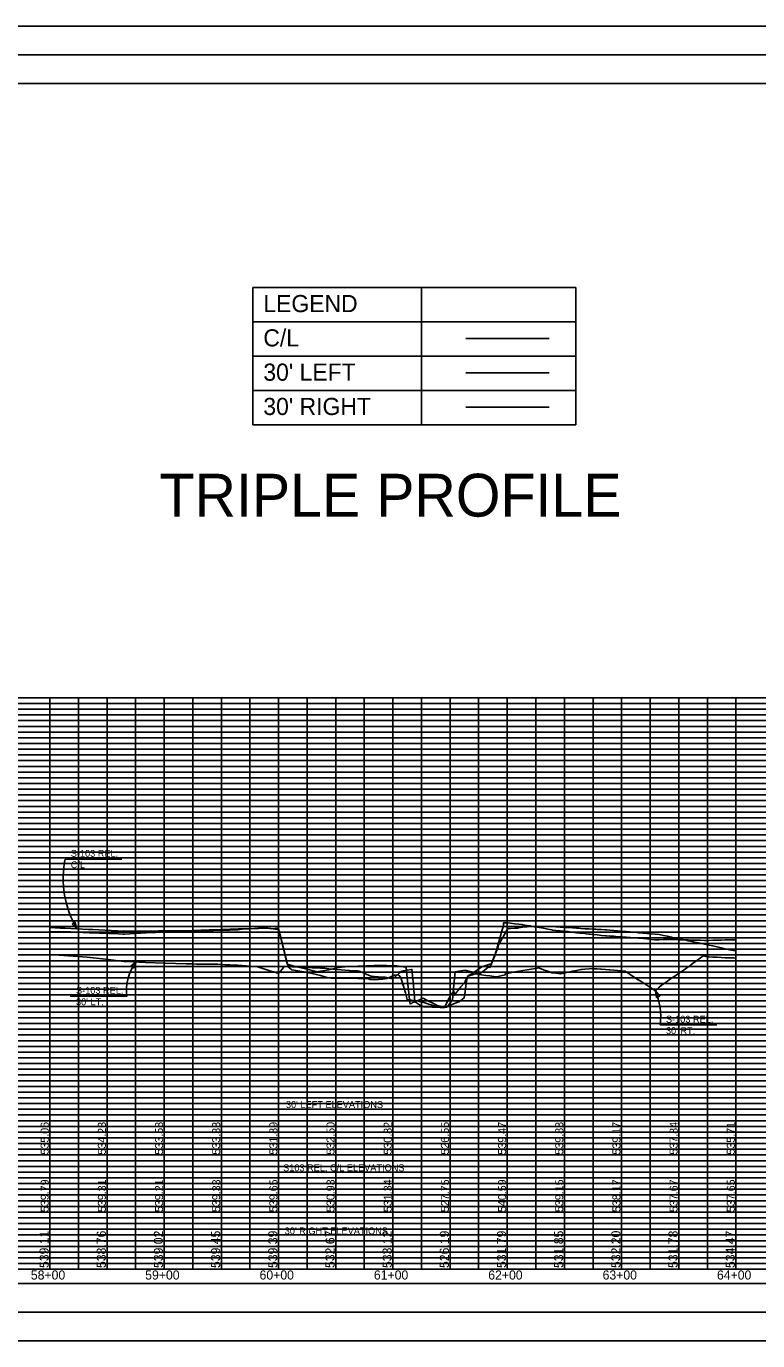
# Model space of a CAD drawing. Extents: x 49817 to 52197, y 49938 to 51088.
# Drawn here: x 50379 to 51019, y 49938 to 51088 of the extents above; entities that cross this region are included whole.
import ezdxf

# ---------------------------------------------------------------- set-up
doc = ezdxf.new("R2010")
doc.units = 0
for name, color, linetype in [('RD_DDB_Profile_EX', 7, 'Continuous'), ('RD_DDB_StaTX', 7, 'Continuous'), ('RD_DDB_StripGrade', 7, 'Continuous'), ('RD_GPK_Profile_Cell', 7, 'Continuous'), ('RD_SHT_Bndy', 7, 'Continuous'), ('RD_SHT_Iplotshp', 7, 'Continuous'), ('RD_SHT_MjGrid', 7, 'Continuous'), ('RD_SHT_MnGrid', 7, 'Continuous'), ('RD_SHT_SubGrid', 7, 'Continuous'), ('RD_TX_Misc2', 7, 'Continuous'), ('RD_TX_Profile', 7, 'Continuous')]:
    doc.layers.add(name, color=color, linetype=linetype)

msp = doc.modelspace()

# ---------------------------------------------------------------- linework, layer by layer
at = {"layer": 'RD_DDB_Profile_EX'}
for points in [[(50750.5, 50239.7), (50752.3, 50242.2), (50753.4, 50243.6), (50753.9, 50239.7), (50755.9, 50242.6), (50756.7, 50243.6), (50759.5, 50247), (50762.5, 50250.5), (50763.2, 50251.9), (50764.2, 50253.9), (50765.6, 50256.1), (50766.2, 50256.9), (50766.8, 50257.3), (50770.4, 50259.7), (50774, 50262.1), (50777.7, 50264.5), (50781.2, 50265.7), (50784.8, 50266.8), (50785.9, 50267.1), (50786.3, 50267.2), (50788.4, 50272.3), (50788.9, 50273.5), (50792, 50284.4), (50795.7, 50297.1), (50796.6, 50300.5), (50796.8, 50303.2), (50799.3, 50303), (50800.3, 50303), (50802.9, 50302.7), (50806.5, 50302.3), (50810.1, 50301.9), (50813.1, 50301.6), (50813.7, 50301.5), (50817.3, 50300.9), (50820.1, 50300.4), (50821, 50300.2), (50823.6, 50299.7), (50824.6, 50299.6), (50828.2, 50298.9), (50831.8, 50298.3), (50835.4, 50297.6), (50839, 50296.9), (50839.4, 50296.8), (50840, 50296.7), (50842.6, 50296.5), (50846.2, 50296.1), (50849.8, 50295.8), (50853, 50295.5), (50853.4, 50295.4), (50857.1, 50294.9), (50860.7, 50294.5), (50863.6, 50294.1), (50864.3, 50294), (50867.9, 50293.7), (50869.1, 50293.6), (50871.5, 50293.3), (50872.4, 50293.2), (50875.1, 50292.9), (50878.7, 50292.5), (50882.3, 50292.1), (50885.9, 50291.7), (50886.7, 50291.7), (50889.6, 50291.5), (50893.2, 50291.3), (50896.8, 50291), (50900.4, 50290.8), (50904, 50290.6), (50907.6, 50290.3), (50910.6, 50290.1), (50911.2, 50290.1), (50911.6, 50290.1), (50914.8, 50289.8), (50918.5, 50289.6), (50919.4, 50289.5), (50922.1, 50289.2), (50925.7, 50288.6), (50928.8, 50288.1), (50929.4, 50288.1), (50932.9, 50288.3), (50936.5, 50288.5), (50939.7, 50288.6), (50940.1, 50288.6), (50943.7, 50288.5), (50947.3, 50288.4), (50951, 50288.3), (50952.6, 50288.3), (50954.6, 50288.2), (50958.2, 50288.1), (50961.8, 50288), (50965.4, 50287.9), (50969, 50287.8), (50972.6, 50287.7), (50976.3, 50287.6), (50979.8, 50287.8), (50983.5, 50287.9), (50986.7, 50288), (50987.1, 50288), (50990.7, 50288.1), (50994.3, 50288.1), (50997.9, 50288.2), (51000, 50288.2)], [(50400, 50299), (50408.9, 50298.5), (50413.5, 50298.3), (50433.9, 50297.3), (50437.5, 50297.2), (50459, 50296.1), (50459.3, 50296.1), (50462.3, 50295.9), (50464.8, 50296), (50487.2, 50295.9), (50495, 50296), (50512.2, 50296), (50521.2, 50296.2), (50523.2, 50296.2), (50524.8, 50296.2), (50528.4, 50296.2), (50532, 50296.3), (50535.6, 50296.3), (50537.2, 50296.3), (50539.2, 50296.4), (50542.9, 50296.5), (50546.5, 50296.6), (50550.1, 50296.7), (50551, 50296.7), (50553.7, 50296.8), (50557.3, 50296.8), (50560.9, 50296.9), (50562.2, 50297), (50563.5, 50297), (50564.5, 50297.1), (50568.1, 50297.5), (50570.8, 50297.8), (50571.7, 50297.8), (50575.4, 50298), (50579, 50298.2), (50582.6, 50298.4), (50586.2, 50298.5), (50588.7, 50298.7), (50589.8, 50298.7), (50593.6, 50298), (50597, 50298.1), (50598.7, 50298.1), (50600, 50298.2), (50600.6, 50295.5), (50601.3, 50292.5), (50604.3, 50281.1), (50607.9, 50267.1), (50608.6, 50264.3), (50611.6, 50262.1), (50615.1, 50261.4), (50618.7, 50260.8), (50622.3, 50260.1), (50625.9, 50259.4), (50628.3, 50259), (50629.5, 50258.7), (50633.1, 50257.8), (50636.8, 50256.9), (50640.4, 50256), (50644, 50255.1), (50645.9, 50254.6), (50647.6, 50254.7), (50651.2, 50254.7), (50654.8, 50254.7), (50655.6, 50254.7), (50658.4, 50254.6), (50662, 50254.6), (50665.6, 50254.6), (50669.3, 50254.5), (50672.9, 50254.5), (50676.5, 50254.4), (50677.9, 50254.4), (50680.1, 50253.4), (50683.8, 50253.2), (50687.3, 50253.5), (50691.1, 50253.9), (50694.7, 50254.3), (50698.2, 50255.9), (50701.3, 50257.3), (50701.8, 50257.3), (50704.8, 50257.5), (50705.4, 50256.9), (50707, 50254.9), (50709, 50248.6), (50711.1, 50241.8), (50712.4, 50236), (50716.2, 50235.5), (50719.8, 50235), (50720.7, 50234.9), (50722.4, 50234.7), (50723.4, 50234.4), (50725.3, 50233.8), (50727, 50233.3), (50730.7, 50232.2), (50734.3, 50231.2), (50737.9, 50230.1), (50741.7, 50228.9), (50744.6, 50228.7), (50745.1, 50229.4), (50745.7, 50230.3), (50748.7, 50236.2), (50750.5, 50239.7)], [(50400, 50295.6), (50409.8, 50295.3), (50418, 50295.1), (50434.7, 50294.4), (50435.2, 50294.4), (50459.9, 50293.4), (50463.9, 50293.2), (50465.3, 50293.3), (50488.8, 50294.6), (50492.5, 50294.7), (50513.8, 50295.8), (50519.4, 50296), (50521.2, 50296.1), (50524.8, 50296.3), (50528.4, 50296.4), (50532, 50296.6), (50535.6, 50296.8), (50539.2, 50296.9), (50542.9, 50297), (50546, 50297.1), (50546.5, 50297.1), (50550.1, 50297.2), (50553.7, 50297.4), (50557.3, 50297.5), (50560.9, 50297.7), (50564.7, 50297.8), (50568.1, 50297.8), (50572, 50297.9), (50575.4, 50298), (50579, 50298.1), (50582.6, 50298.2), (50586.2, 50298.3), (50589.8, 50298.5), (50590.2, 50298.5), (50593.4, 50298.1), (50597, 50297.7), (50599.5, 50297.4), (50600.3, 50296.7), (50600.6, 50295.3), (50604.3, 50280.5), (50607.6, 50266.8), (50611.5, 50265.9), (50615.1, 50265), (50618.7, 50264.1), (50622.3, 50263.2), (50625.9, 50262.3), (50629.5, 50261.4), (50631.8, 50260.8), (50633.1, 50260.4), (50634.5, 50260.1), (50635.3, 50260.4), (50636.8, 50260.7), (50640.4, 50261.4), (50644, 50262.1), (50647.6, 50262.9), (50651.2, 50263.6), (50655, 50264.4), (50658.4, 50264.6), (50662, 50264.8), (50665.6, 50264.9), (50669.3, 50265.1), (50672.9, 50265.3), (50676.5, 50265.5), (50678.2, 50265.6), (50680.1, 50265.6), (50683.7, 50265.7), (50685.7, 50265.7), (50687.3, 50265.7), (50690.9, 50265.7), (50694.5, 50265.7), (50698.2, 50265.6), (50701.8, 50265.6), (50703.3, 50265.6), (50705.4, 50265.2), (50709, 50264.6), (50711.7, 50264.2), (50712.6, 50255), (50714.7, 50233.5), (50715, 50232.2), (50716.2, 50232.6), (50717, 50233), (50719.8, 50234.2), (50723.4, 50235.7), (50726.6, 50237.1), (50727, 50236.9), (50730.7, 50235), (50734.3, 50233.2), (50737.9, 50231.4), (50738.8, 50230.9), (50741.5, 50230.2), (50745.1, 50229.3), (50745.5, 50229.2), (50748.7, 50230.4), (50752.3, 50231.9), (50755.9, 50233.3), (50758.2, 50234.1), (50759.5, 50235.2), (50762.3, 50237.4), (50763.2, 50243.1), (50764.2, 50250.2), (50765.1, 50256.2)], [(50775.9, 50258.9), (50776.3, 50258.8), (50777.6, 50259.6), (50781.2, 50262.6), (50783.4, 50264.3), (50784.8, 50263.9), (50788.4, 50272.7), (50791.3, 50279.8), (50792, 50282.4), (50792.5, 50284), (50795.7, 50289.5), (50797.6, 50292.9), (50799.3, 50296), (50800.4, 50298.1), (50802.9, 50298.2), (50806.5, 50298.3), (50809.1, 50298.4), (50810.1, 50298.6), (50813.2, 50299.3), (50813.7, 50299.3), (50817.3, 50299.6), (50820.9, 50299.8), (50824.6, 50300), (50825.3, 50300.1), (50828.2, 50300), (50831.8, 50299.9), (50835.4, 50299.8), (50836.2, 50299.8), (50837.9, 50299.9), (50839, 50299.8), (50842.6, 50299.6), (50846.2, 50299.4), (50849.8, 50299.1), (50850.5, 50299.1), (50853.4, 50298.9), (50857.1, 50298.7), (50860.7, 50298.5), (50862.2, 50298.4), (50864.3, 50298.2), (50867.9, 50298), (50871.5, 50297.8), (50875.1, 50297.6), (50877.4, 50297.5), (50878.7, 50297.4), (50882.3, 50297.2), (50885.6, 50297), (50885.9, 50297), (50887, 50296.9), (50889.6, 50296.7), (50893.2, 50296.4), (50896.5, 50296.2), (50896.8, 50296.2), (50900.4, 50295.8), (50904, 50295.5), (50907.6, 50295.1), (50911.2, 50294.8), (50911.6, 50294.8), (50914.8, 50294.5), (50916.3, 50294.4), (50918.5, 50294.2), (50922.1, 50293.9), (50925.7, 50293.5), (50929.3, 50293.2), (50932.9, 50292.8), (50934.2, 50292.7), (50936.5, 50292.1), (50940.1, 50291.3), (50943.7, 50290.6), (50947.3, 50289.8), (50951, 50289), (50954.6, 50288.2), (50957.4, 50287.7), (50958.2, 50287.5), (50961.8, 50286.7), (50963.5, 50286.3), (50965.4, 50285.9), (50969, 50285.2), (50972.6, 50284.4), (50976.2, 50283.7), (50979.4, 50283.1), (50979.8, 50283), (50983.5, 50282.1), (50987.1, 50281.3), (50990.7, 50280.4), (50994.3, 50279.6), (50996.2, 50279.1), (50997.9, 50278.9), (51000, 50278.5)], [(50400, 50275.3), (50432.7, 50273.2), (50448.7, 50271.3), (50464.8, 50269.4), (50467.2, 50269.2), (50483.6, 50268.5), (50501, 50267.9), (50519.3, 50267.2), (50521.2, 50267.1), (50524.8, 50267.1), (50528.4, 50267), (50532, 50267), (50535.6, 50266.9), (50539.2, 50266.9), (50542.9, 50266.8), (50546.5, 50266.8), (50550.1, 50266.6), (50553.7, 50266.5), (50557.3, 50266.4), (50560.9, 50266.2), (50562.9, 50266.1), (50564.5, 50266), (50568.1, 50265.7), (50571.7, 50265.5), (50575.4, 50265.2), (50579, 50264.9), (50581.3, 50264.8), (50582.6, 50264.3), (50586.2, 50263.2), (50589.8, 50262.1), (50593.4, 50260.9), (50597, 50259.8), (50598.2, 50259.4), (50600.6, 50259.5), (50604.3, 50263.9), (50605.1, 50264.9), (50607.9, 50264.8), (50611.5, 50264.6), (50615.1, 50264.5), (50618.7, 50264.3), (50622.3, 50264.1), (50625.9, 50263.9), (50629.5, 50263.8), (50633.1, 50263.6), (50636.8, 50263.4), (50639.8, 50263.3), (50640.4, 50263.3), (50644, 50263), (50647.6, 50262.7), (50651.2, 50262.4), (50654.8, 50262.1), (50658.4, 50261.8), (50662, 50261.5), (50665.6, 50261.2), (50669.3, 50261), (50670.6, 50260.9), (50672.9, 50259.8), (50676.5, 50258.2), (50680.1, 50256.6), (50680.9, 50256.3), (50683.7, 50256.1), (50687.3, 50255.9), (50690.9, 50255.7), (50693.3, 50255.5), (50694.5, 50255.3), (50698.2, 50254.5), (50700.1, 50254.1), (50701.8, 50255.7), (50705.4, 50259.2), (50706.8, 50260.6), (50709, 50261), (50712.6, 50261.7), (50716.2, 50262.4), (50716.7, 50262.5), (50717.8, 50251.4), (50719.2, 50234.2), (50719.8, 50233.8), (50723.4, 50231.5), (50724.4, 50230.9), (50727.1, 50229.6), (50730.7, 50229.5), (50734.3, 50229.4), (50737.9, 50229.3), (50741.5, 50229.2), (50743.3, 50229.2), (50745.1, 50229.2), (50747.2, 50229.3), (50748.3, 50230.5), (50748.7, 50231.1), (50752.2, 50235.6), (50753.4, 50248.9), (50754.5, 50260.2), (50755.9, 50260.5), (50759.5, 50261.1), (50763.2, 50261.6), (50766.8, 50260.8), (50770.4, 50260), (50774, 50259.2), (50774.6, 50259.1), (50775.4, 50259.2), (50775.9, 50258.9)], [(50765.1, 50256.2), (50766.8, 50256.8), (50770.4, 50258), (50771.7, 50258.4), (50774, 50258.1), (50777.6, 50257.6), (50781.2, 50257.1), (50784.8, 50256.6), (50788.4, 50256.1), (50790.7, 50255.8), (50792, 50256.1), (50795.7, 50256.9), (50797.5, 50257.3), (50798.8, 50258.9), (50799.3, 50258.9), (50800, 50258.9), (50802.9, 50259.5), (50806.5, 50260.1), (50810.1, 50260.7), (50813.7, 50261.3), (50817.3, 50261.9), (50820.9, 50262.5), (50824.6, 50263.1), (50827.8, 50263.6), (50828.2, 50263.5), (50831.8, 50262.1), (50835.4, 50260.8), (50837, 50260.1), (50839.1, 50259.4), (50842.6, 50259), (50846.2, 50258.6), (50846.7, 50258.5), (50849.8, 50259.2), (50853.4, 50260), (50856.2, 50260.5), (50857.1, 50260.7), (50860.7, 50261.4), (50864.3, 50262.2), (50865.6, 50262.4), (50867.9, 50262.7), (50871.5, 50263), (50873, 50263.2), (50875.1, 50263), (50878.7, 50262.8), (50881.5, 50262.6), (50882.3, 50262.5), (50885.9, 50262.2), (50889.2, 50261.9), (50889.6, 50261.9), (50893.2, 50261.6), (50896.8, 50261.3), (50900.4, 50261), (50903, 50260.7), (50904, 50260.1), (50907.6, 50257.8), (50911.2, 50255.4), (50914.5, 50253.3), (50914.8, 50253.1), (50918.5, 50250.8), (50922.1, 50248.5), (50925.7, 50246.2), (50929.6, 50243.7), (50932.9, 50246.8), (50934.5, 50248.4), (50936.5, 50249.7), (50940.1, 50252.2), (50941.7, 50253.3), (50943.7, 50254.6), (50947.3, 50257.1), (50951, 50259.6), (50954.6, 50262), (50958.2, 50264.5), (50959.3, 50265.3), (50961.8, 50267.1), (50965.4, 50269.8), (50969, 50272.5), (50971.3, 50274.2), (50972.6, 50273.9), (50975.5, 50273.4), (50976.2, 50273.4), (50979.8, 50273.2), (50983.5, 50273), (50987.1, 50272.8), (50990.7, 50272.6), (50994.3, 50272.5), (50996.8, 50272.4), (50997.9, 50272.4), (51000, 50272.3)]]:
    msp.add_lwpolyline(points, dxfattribs=at)
at = {"layer": 'RD_GPK_Profile_Cell'}
msp.add_line((50000, 50000), (52196.9, 50000), dxfattribs=at)
at = {"layer": 'RD_SHT_Bndy'}
for p, q in [((51590.7, 51087.5), (49830.7, 51087.5)), ((51590.7, 51062.5), (49830.7, 51062.5)), ((49913, 50500), (51588, 50500)), ((49913, 50000), (51588, 50000)), ((51590.7, 49962.5), (49830.7, 49962.5)), ((51590.7, 49937.5), (49830.7, 49937.5))]:
    msp.add_line(p, q, dxfattribs=at)
msp.add_lwpolyline([(49913.1, 51037.5), (51588, 51037.5), (51588, 49987.5), (49913.1, 49987.5)], close=True, dxfattribs=at)
at = {"layer": 'RD_SHT_Iplotshp'}
msp.add_lwpolyline([(49817.1, 51062.5), (51613, 51062.5), (51613, 49962.5), (49817.1, 49962.5)], close=True, dxfattribs=at)
at = {"layer": 'RD_SHT_MjGrid'}
for p, q in [((50400, 50500), (50400, 50000)), ((50450, 50500), (50450, 50000)), ((50500, 50500), (50500, 50000)), ((50550, 50500), (50550, 50000)), ((50600, 50500), (50600, 50000)), ((50650, 50500), (50650, 50000)), ((50700, 50500), (50700, 50000)), ((50750, 50500), (50750, 50000)), ((50800, 50500), (50800, 50000)), ((50850, 50500), (50850, 50000)), ((50900, 50500), (50900, 50000)), ((50950, 50500), (50950, 50000)), ((51000, 50500), (51000, 50000)), ((49913, 50450), (51588, 50450)), ((49913, 50400), (51588, 50400)), ((49913, 50350), (51588, 50350)), ((49913, 50300), (51588, 50300)), ((49913, 50250), (51588, 50250)), ((49913, 50200), (51588, 50200)), ((49913, 50150), (51588, 50150)), ((49913, 50100), (51588, 50100)), ((49913, 50050), (51588, 50050))]:
    msp.add_line(p, q, dxfattribs=at)
at = {"layer": 'RD_SHT_MnGrid'}
for p, q in [((50425, 50500), (50425, 50000)), ((50475, 50500), (50475, 50000)), ((50525, 50500), (50525, 50000)), ((50575, 50500), (50575, 50000)), ((50625, 50500), (50625, 50000)), ((50675, 50500), (50675, 50000)), ((50725, 50500), (50725, 50000)), ((50775, 50500), (50775, 50000)), ((50825, 50500), (50825, 50000)), ((50875, 50500), (50875, 50000)), ((50925, 50500), (50925, 50000)), ((50975, 50500), (50975, 50000)), ((49913, 50475), (51588, 50475)), ((49913, 50425), (51588, 50425)), ((49913, 50375), (51588, 50375)), ((49913, 50325), (51588, 50325)), ((49913, 50275), (51588, 50275)), ((49913, 50225), (51588, 50225)), ((49913, 50175), (51588, 50175)), ((49913, 50125), (51588, 50125)), ((49913, 50075), (51588, 50075)), ((49913, 50025), (51588, 50025))]:
    msp.add_line(p, q, dxfattribs=at)
at = {"layer": 'RD_SHT_SubGrid'}
for p, q in [((49950.1, 50495), (51549.8, 50495)), ((49950.1, 50490), (51549.3, 50490)), ((49950.1, 50485), (51549.8, 50485)), ((49950.1, 50480), (51549.8, 50480)), ((49950.1, 50470), (51549.8, 50470)), ((49950.1, 50465), (51548.8, 50465)), ((49950.1, 50460), (51549.3, 50460)), ((49950.1, 50455), (51549.8, 50455)), ((49950.1, 50445), (51549.8, 50445)), ((49950.1, 50440), (51549.8, 50440)), ((49950.1, 50435), (51549.3, 50435)), ((49950.1, 50430), (51549.8, 50430)), ((49950.1, 50420), (51548.8, 50420)), ((49950.1, 50415), (51548.8, 50415)), ((49950.1, 50410), (51549.3, 50410)), ((49950.1, 50405), (51549.3, 50405)), ((49950.1, 50395), (51548.8, 50395)), ((49950.1, 50390), (51549.3, 50390)), ((49950.1, 50385), (51548.8, 50385)), ((49950.1, 50380), (51549.8, 50380)), ((49950.1, 50370), (51549.3, 50370)), ((49950.1, 50365), (51549.3, 50365)), ((49950.1, 50360), (51549.3, 50360)), ((49950.1, 50355), (51549.3, 50355)), ((49950.2, 50345), (51548.8, 50345)), ((49950.2, 50340), (51548.8, 50340)), ((49950.1, 50335), (51549.3, 50335)), ((49950.1, 50330), (51549.3, 50330)), ((49950.1, 50320), (51549.3, 50320)), ((49950.1, 50315), (51549.3, 50315)), ((49950.1, 50310), (51548.8, 50310)), ((49950.1, 50305), (51549.3, 50305)), ((49950.1, 50305), (51549.3, 50305)), ((49950.1, 50295), (51549.8, 50295)), ((49950.1, 50290), (51549.8, 50290)), ((49950.1, 50285), (51549.8, 50285)), ((49950.1, 50280), (51549.8, 50280)), ((49950.1, 50270), (51549.8, 50270)), ((49950.1, 50265), (51549.8, 50265)), ((49950.1, 50260), (51549.8, 50260)), ((49950.1, 50255), (51549.8, 50255)), ((49950.1, 50245), (51549.9, 50245)), ((49950.1, 50240), (51549.9, 50240)), ((49950.1, 50235), (51549.9, 50235)), ((49950.1, 50230), (51549.9, 50230)), ((49950.1, 50220), (51549.9, 50220)), ((49950.1, 50215), (51549.9, 50215)), ((49950.1, 50210), (51549.9, 50210)), ((49950.1, 50205), (51549.9, 50205)), ((49950.1, 50195), (51549.9, 50195)), ((49950.1, 50190), (51549.9, 50190)), ((49950.1, 50185), (51549.9, 50185)), ((49950.1, 50180), (51549.9, 50180)), ((49950.1, 50170), (51549.9, 50170)), ((49950.1, 50170), (51549.9, 50170)), ((49950.1, 50165), (51549.9, 50165)), ((49950.1, 50160), (51549.6, 50160)), ((49950.1, 50155), (51549.6, 50155)), ((49950.1, 50145), (51549.8, 50145)), ((49950.1, 50140), (51550, 50140)), ((49950.1, 50135), (51550, 50135)), ((49950.1, 50130), (51550, 50130)), ((49950.1, 50120), (51550, 50120)), ((49950.1, 50115), (51550, 50115)), ((49950.1, 50110), (51550, 50110)), ((49950.1, 50105), (51550, 50105)), ((49950.1, 50095), (51550, 50095)), ((49950.1, 50090), (51550, 50090)), ((49950.1, 50085), (51550, 50085)), ((49950.1, 50080), (51549.9, 50080)), ((49950.1, 50070), (51549.6, 50070)), ((49950.1, 50065), (51549.9, 50065)), ((49950.1, 50060), (51549.9, 50060)), ((49950.1, 50055), (51549.9, 50055)), ((49950.1, 50040), (51549.9, 50040)), ((49950.2, 50045), (51549.9, 50045)), ((49950.1, 50035), (51549.9, 50035)), ((49950.1, 50030), (51549.9, 50030)), ((49950.2, 50020), (51549.9, 50020)), ((49950.2, 50015), (51549.9, 50015)), ((49950.2, 50010), (51549.9, 50010)), ((49950.2, 50005), (51549.9, 50005))]:
    msp.add_line(p, q, dxfattribs=at)
at = {"layer": 'RD_TX_Misc2'}
for p, q in [((50577.6, 50858.9), (50859.9, 50858.9)), ((50577.6, 50858.9), (50577.6, 50738.9)), ((50724.9, 50858.9), (50724.9, 50738.9)), ((50859.9, 50858.9), (50859.9, 50738.9)), ((50577.6, 50828.9), (50859.9, 50828.9)), ((50763.8, 50814.2), (50836.8, 50814.2)), ((50577.6, 50798.9), (50859.9, 50798.9)), ((50763.8, 50784.2), (50836.8, 50784.2)), ((50577.6, 50768.9), (50859.9, 50768.9)), ((50763.8, 50754.2), (50836.8, 50754.2)), ((50577.6, 50738.9), (50859.9, 50738.9))]:
    msp.add_line(p, q, dxfattribs=at)
at = {"layer": 'RD_TX_Profile'}
for p, q in [((50462.9, 50358.9), (50413.3, 50358.9)), ((50467.5, 50239), (50417.9, 50239)), ((50983.4, 50213.8), (50933.8, 50213.8))]:
    msp.add_line(p, q, dxfattribs=at)
for points in [[(50419.5, 50302), (50423.7, 50297.8), (50422.1, 50303.6)], [(50473.1, 50263.3), (50475.4, 50268.9), (50470.7, 50265.2)], [(50933.3, 50239), (50929.6, 50243.7), (50930.4, 50237.8)]]:
    msp.add_lwpolyline(points, close=True, dxfattribs=at)
for centre, radius, start, end in [((50499.6, 50342.1), 87.9, 168.9752, 210.284), ((50507.8, 50244.3), 40.7, 142.7953, 187.4846), ((50876.3, 50220.9), 57.9, 352.964, 23.185)]:
    msp.add_arc(centre, radius, start, end, dxfattribs=at)

# ---------------------------------------------------------------- texts
at = {"layer": 'RD_DDB_StaTX'}
for s, p in [('58+00', (50383.4, 49991)), ('59+00', (50483.4, 49991)), ('60+00', (50583.4, 49991)), ('61+00', (50683.4, 49991)), ('62+00', (50783.4, 49991)), ('63+00', (50883.4, 49991)), ('64+00', (50983.4, 49991))]:
    msp.add_text(s, height=8, dxfattribs=at).set_placement(p)
at = {"layer": 'RD_DDB_StripGrade'}
for s, height, p in [('535.06', 7, (50399, 50100.3)), ('534.23', 7, (50449, 50100.3)), ('533.58', 7, (50499, 50100.3)), ('533.33', 7, (50549, 50100.3)), ('532.50', 7, (50649, 50100.3)), ('526.55', 7, (50749, 50100.3)), ('539.83', 7, (50849, 50100.3)), ('537.84', 7, (50949, 50100.3)), ('531.89', 7, (50599, 50100.3)), ('530.82', 7, (50699, 50100.3)), ('539.47', 7, (50799, 50100.3)), ('539.17', 7, (50899, 50100.3)), ('535.71', 7, (50999, 50100.3)), ('539.79', 7, (50399, 50050)), ('539.31', 7, (50449, 50050)), ('539.21', 7, (50499, 50050)), ('539.33', 7, (50549, 50050)), ('539.65', 7, (50599, 50050)), ('530.93', 7, (50649, 50050)), ('531.34', 7, (50699, 50050)), ('527.75', 7, (50749, 50050)), ('540.59', 7, (50799, 50050)), ('539.15', 7, (50849, 50050)), ('538.17', 7, (50899, 50050)), ('537.67', 7, (50949, 50050)), ('537.65', 7, (50999, 50050)), ('539.11', 8, (50399, 50001.1)), ('538.76', 8, (50449, 50001.1)), ('539.02', 8, (50499, 50001.1)), ('539.45', 8, (50549, 50001.1)), ('539.39', 8, (50599, 50001.1)), ('532.67', 8, (50649, 50001.1)), ('533.12', 8, (50699, 50001.1)), ('526.19', 8, (50749, 50001.1)), ('531.79', 8, (50799, 50001.1)), ('531.85', 8, (50849, 50001.1)), ('532.20', 8, (50899, 50001.1)), ('531.78', 8, (50949, 50001.1)), ('534.47', 8, (50999, 50001.1))]:
    msp.add_text(s, height=height, rotation=90, dxfattribs=at).set_placement(p)
at = {"layer": 'RD_TX_Misc2'}
for s, height, p in [('LEGEND', 15, (50586.7, 50837.4)), ('C/L ', 15, (50586.7, 50807.4)), ("30' LEFT", 15, (50586.7, 50777.4)), ("30' RIGHT", 15, (50586.7, 50747.4)), ('TRIPLE PROFILE', 37.5, (50495.9, 50658.5))]:
    msp.add_text(s, height=height, dxfattribs=at).set_placement(p)
at = {"layer": 'RD_TX_Profile'}
for s, p in [('S-103 REL.', (50418.3, 50360.9)), ('C/L', (50418.3, 50350.9)), ('S-103 REL.', (50422.9, 50241)), ("30' LT.", (50422.9, 50231)), ('S-103 REL.', (50938.8, 50215.8)), ("30' RT.", (50938.8, 50205.8)), ("30' LEFT ELEVATIONS", (50606.5, 50141.1)), ('S103 REL. C/L ELEVATIONS', (50604, 50085.8)), ("30' RIGHT ELEVATIONS", (50605.4, 50030.6))]:
    msp.add_text(s, height=6, dxfattribs=at).set_placement(p)

doc.saveas('drawing.dxf')
